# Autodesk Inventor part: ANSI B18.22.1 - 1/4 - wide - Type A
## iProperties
Comments: To add or edit properties for Autodesk Inventor files, use iProperties.
Created: 2005-06
Part Number: ANSI B18.22.1 - 1/4 - wide - Type A
Vendor: Autodesk Inc.
Document SubType Name: Modeling
Designer: John Blackburn
Material: Default
Description: Washer A
Standard: ANSI B18.22.1
Size Designation: 1/4 - wide - Type A
Alert: To add or edit properties for Autodesk Inventor files, use iProperties.
Control State: 0
Master: False
Checked Out: False
Shininess: 64.0
Length Units: 11272
Angle Units: 11279
Time Units: 11290
Mass Units: 11286
Length Display Precision: 3
Angle Display Precision: 2
Compacted: True
Classification: un/spsc 31161807
Density: 0.0
Volumn: 0.0
Area: 0.0
PropertySet Name: Model Information
Author: John Blackburn
Revision Number: 8
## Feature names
1. Body [Extrusion]
